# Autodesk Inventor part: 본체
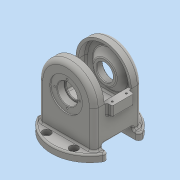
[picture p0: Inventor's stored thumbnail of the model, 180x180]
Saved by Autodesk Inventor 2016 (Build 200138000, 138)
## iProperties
Created: 2024-08
Part Number: 본체
Material: 일반
Document SubType Name: Modeling
Designer: pc-7
Density: 1 g/cm^3
Appearance: 기본값
Author: pc-7
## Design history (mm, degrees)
sketch "스케치1"
  geometry: C1 r 71 at (0, 0); 1 further point
  constraints: 1 centre point, 1 coincident
  dimensions: "d0" = 142 diameter of C1
extrude "돌출1" new body sketch "스케치1" distance "d1" = 13; taper "d2" = 0 deg
sketch "스케치2"
  geometry: L1 (-51, 81)-(51, 81); L2 (51, 81)-(51, 13); L3 (51, 13)-(-51, 13); L4 (-51, 13)-(-51, 81); L5 (71, 13)-(-71, 13) reference; L6 (-71, 0)-(71, 0) reference; A1 r 51 centre (0, 81) between (51, 81) and (-51, 81); A2 r 51 centre (0, 81) between (-51, 81) and (51, 81); 2 further points
  constraints: 8 end point, 4 point on circle, 3 midpoint, 2 centre point, 2 parallel, 1 horizontal, 1 perpendicular, 1 vertical alignment
  dimensions: "d3" = 81 distance from line of L6 A1.centre; "d4" = 102 diameter of A1
extrude "돌출2" join sketch "스케치2" stored distance "d5" = 88; taper "d6" = 0 deg
sketch "스케치3"
  geometry: L1 (19, 28)-(0, 28); L2 (0, 28)-(0, -28); L3 (0, -28)-(19, -28); L4 (19, -28)-(19, 28); 2 further points
  constraints: 8 end point, 2 parallel, 1 coincident, 1 horizontal, 1 midpoint, 1 perpendicular
  dimensions: "d7" = 19 distance between parallel lines of L2 L4; "d8" = 56 distance between parallel lines of L3 L1
extrude "돌출3" cut sketch "스케치3" stored distance "d9" = 88; taper "d10" = 0 deg
node "작업 평면1"
sketch "스케치4"
  geometry: L1 (-61, -20)-(61, -20); L2 (61, -20)-(61, 20); L3 (61, 20)-(-61, 20); L4 (-61, 20)-(-61, -20); L5 (-61, -20)-(61, 20); L6 (61, -20)-(-61, 20); 1 further point
  constraints: 12 end point, 2 midpoint, 2 parallel, 1 horizontal, 1 perpendicular
  dimensions: "d15" = 122 distance between parallel lines of L2 L4; "d16" = 40 distance between parallel lines of L1 L3
extrude "돌출4" join sketch "스케치4" distance "d17" = 20; taper "d18" = 0 deg
sketch "스케치5"
  geometry: L1 (-51, 13)-(-51, 81) reference; L2 (51, 81)-(51, 13) reference; L3 (-51, 13)-(51, 13) reference; L4 (-46, 81)-(-46, 40); L5 (46, 40)-(46, 81); L6 (65.246, 0)-(-65.246, 0) reference; L7 (-46, 40)-(46, 40); A1 r 51 centre (0, 81) between (51, 81) and (-51, 81) reference; A2 r 46 centre (0, 81) between (46, 81) and (-46, 81); 1 further point
  constraints: 6 end point, 2 point on circle, 1 centre point, 1 other
  dimensions: "d21" = 5 distance between parallel lines of L2 L5; "d22" = 40 distance from line of L6 L4.end; "d23" = 40 distance from line of L6 L5.start; "d24" = 5 distance between parallel lines of L1 L4
extrude "돌출5" cut sketch "스케치5" stored distance "d25" = 78; taper "d26" = 0 deg
sketch "스케치6"
  geometry: L1 (132, 25)-(81, 25); L2 (81, 25)-(81, -25); L3 (81, -25)-(132, -25); L4 (132, -25)-(132, 25); L5 (132, -44)-(132, 44) reference; L6 (0, -28)-(0, -71) reference; 3 further points
  constraints: 8 end point, 3 midpoint, 2 parallel, 1 horizontal, 1 horizontal alignment, 1 perpendicular
  dimensions: "d27" = 50 distance between parallel lines of L3 L1; "d28" = 81 distance between parallel lines of L6 L2
extrude "돌출6" cut sketch "스케치6" stored distance "d29" = 78; taper "d30" = 0 deg
sketch "스케치7"
  geometry: C1 r 33.5 at (0, 81); 1 further point
  constraints: 1 centre point, 1 vertical alignment
  dimensions: "d31" = 81 distance of point (0, 0) C1.centre; "d32" = 67 diameter of C1
extrude "돌출7" join sketch "스케치7" distance "d33" = 12; taper "d34" = 0 deg
feature "면 기울기1" dims angle "d35" = 45 deg
feature "면 기울기2" dims angle "d36" = 45 deg
sketch "스케치8"
  geometry: C1 r 21.5 at (0, 81) reference; 2 further points
  constraints: 1 coincident
hole "구멍1" sketch "스케치8" at (0, 81) diameter "d37" = 37; stored, may be unused: countersink angle "d41" = 90 deg, drill point angle "d43" = 0 deg; dims "d38" = 6, "d39" = 60, "d40" = 2, "d42" = 15
hole "구멍2" diameter "d46" = 32; stored, may be unused: countersink angle "d50" = 90 deg, drill point angle "d52" = 0 deg; dims "d44" = 10, "d45" = 10, "d47" = 6, "d48" = 67, "d49" = 2, "d51" = 15
sketch "스케치9"
  geometry: C1 r 30 at (0, 0); 1 further point
  constraints: 1 centre point, 1 coincident
  dimensions: "d53" = 60 diameter of C1
extrude "돌출8" cut sketch "스케치9" distance "d54" = 22; taper "d55" = 0 deg
hole "구멍3" diameter "d58" = 22; stored, may be unused: countersink angle "d62" = 90 deg, drill point angle "d64" = 0 deg; dims "d56" = 10, "d57" = 10, "d59" = 6, "d60" = 28, "d61" = 15, "d63" = 15
sketch "스케치10" dims "d65" = 46
  geometry: L1 (-51, 0)-(-51, -68) reference; L2 (51, -68)-(-51, -68) reference; L3 (51, -68)-(51, 0) reference; C1 r 30 at (0, 0) reference; A1 r 51 centre (0, 0) between (51, 0) and (-51, 0) reference; 3 further points
  constraints: 2 vertical alignment, 1 coincident, 2 other
hole "구멍4" sketch "스케치10" at (0, 23) diameter "d66" = 3.242; stored, may be unused: countersink angle "d70" = 90 deg, drill point angle "d72" = 118 deg; dims "d67" = 8, "d68" = 28, "d69" = 15, "d71" = 10
sketch "스케치11"
  geometry: 2 further points
  dimensions: "d76" = 13 vertical distance of point (0, 0) point (-54, 13); "d77" = 54 horizontal distance of point (-54, 13) point (0, 0)
hole "구멍5" sketch "스케치11" at (-54, 13) diameter "d78" = 3.242; stored, may be unused: countersink angle "d82" = 90 deg, drill point angle "d84" = 118 deg; dims "d79" = 8, "d80" = 28, "d81" = 15, "d83" = 10
sketch "스케치12" dims "d91" = 46
  geometry: 3 further points
  constraints: 2 vertical alignment, 1 coincident, 2 other
hole "구멍6" sketch "스케치12" at (0, 23) diameter "d92" = 3.242; stored, may be unused: countersink angle "d96" = 90 deg, drill point angle "d98" = 118 deg; dims "d93" = 8, "d94" = 28, "d95" = 15, "d97" = 10
sketch "스케치13"
  geometry: 2 further points
  dimensions: "d102" = 25 horizontal distance of point (0, 0) point (-25, -55); "d103" = 55 vertical distance of point (0, 0) point (-25, -55)
hole "구멍7" sketch "스케치13" at (-25, -55) diameter "d104" = 9; stored, may be unused: countersink angle "d108" = 90 deg, drill point angle "d110" = 0 deg; dims "d105" = 8, "d106" = 15, "d107" = 8.8, "d109" = 10
fillet "모깎기1" dims "d117" = 6
fillet "모깎기2" dims "d118" = 8
fillet "모깎기3" dims "d119" = 3
fillet "모깎기4" dims "d120" = 3
fillet "모깎기5" dims "d121" = 3
fillet "모깎기6" dims "d122" = 3
fillet "모깎기7" dims "d123" = 3
fillet "모깎기8" dims "d124" = 3
fillet "모깎기9" dims "d125" = 3
fillet "모깎기10" dims "d126" = 3
fillet "모깎기11" dims "d127" = 3
fillet "모깎기12" dims "d128" = 3
fillet "모깎기13" dims "d129" = 3
fillet "모깎기14" dims "d130" = 3
chamfer "모따기1" distance "d131" = 1; stored, may be unused: second distance "d132" = 2, angle "d133" = 45 deg
chamfer "모따기2" distance "d134" = 1; stored, may be unused: second distance "d135" = 2, angle "d136" = 45 deg
chamfer "모따기3" distance "d137" = 1; stored, may be unused: second distance "d138" = 2, angle "d139" = 45 deg
fillet "모깎기15" dims "d140" = 0.3
fillet "모깎기16" dims "d141" = 0.3
fillet "모깎기17" dims "d142" = 3
fillet "모깎기18" dims "d143" = 3
fillet "모깎기19" dims "d144" = 3
sketch "스케치14"
  geometry: L1 (-24.887, 33.602)-(24.887, 33.602); L2 (24.887, 33.602)-(24.887, 26.398); L3 (24.887, 26.398)-(-24.887, 26.398); L4 (-24.887, 26.398)-(-24.887, 33.602); L5 (-24.887, 30)-(24.887, 30); L6 (0, 33.602)-(0, 26.398); L7 (-60.512, 0)-(60.512, 0) reference; 3 further points
  constraints: 6 midpoint, 4 end point, 1 vertical alignment, 2 other
  dimensions: "d145" = 30 distance from line of L7 point (0, 30)
feature "엠보싱1" sketch "스케치14" dims "d7" = 19, "d8" = 56, "d146" = 0.5, "d147" = 0
node "솔리드1"
mirror "대칭1"
mirror "대칭2"
pattern_circular "원형 패턴1" dims angle "d74" = 360 deg
mirror "대칭3"
pattern_linear "직사각형 패턴1" dims "d87" = 26
pattern_linear "직사각형 패턴2" dims "d90" = 108
pattern_circular "원형 패턴2" dims angle "d100" = 360 deg
pattern_linear "직사각형 패턴3" dims "d113" = 50
node "투영된 루프1"
node "투영된 루프2"
other parameters: "d11" = 68
